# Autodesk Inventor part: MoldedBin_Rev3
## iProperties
Created: 2008-11
Part Number: MoldedBin_Rev3
Document SubType Name: Modeling
Designer: ETUDIANT
Norme de conversion: STEP AP214IS
Nom du fichier: MoldedBin_Rev3.STEP
Préprocesseur: SolidWorks 2008
Postprocesseur: Build: 344a, Release: 11 SP2 - Date: Fri 08/18/2006
Unités envoyées: INCHES
Incertitude: 1e-05
Author: ETUDIANT
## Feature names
1. Base1
